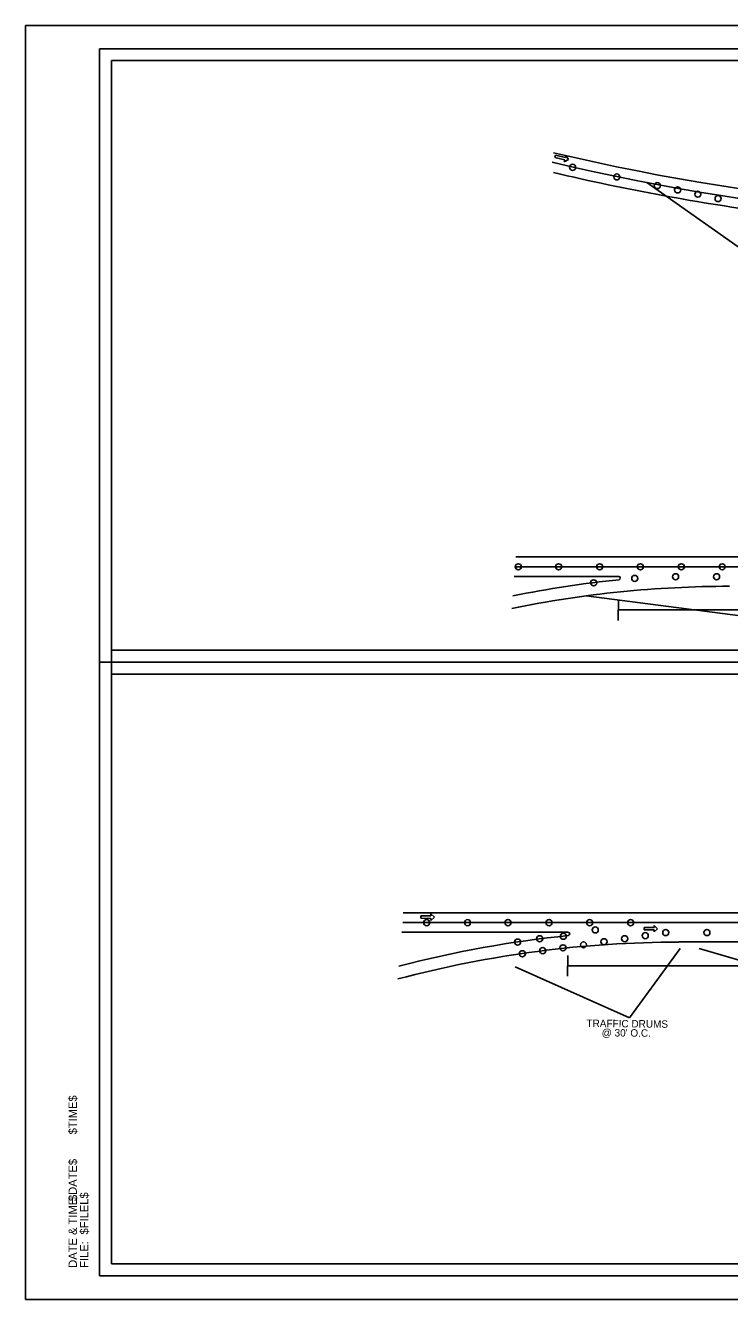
# Model space of a CAD drawing. Extents: x 13528 to 25043, y 7635 to 10612.
# Drawn here: x 17592 to 18181, y 9545 to 10612 of the extents above; entities that cross this region are included whole.
import ezdxf

# ---------------------------------------------------------------- set-up
doc = ezdxf.new("R2010")
doc.units = 0
for name, color, linetype in [('Default', 7, 'Continuous'), ('R_Border', 7, 'Continuous'), ('R_Border Notes', 7, 'Continuous'), ('R_Border Plan-Plan', 7, 'Continuous'), ('R_Draft', 7, 'Continuous'), ('R_Revision Date Text', 7, 'Continuous')]:
    doc.layers.add(name, color=color, linetype=linetype)

# ---------------------------------------------------------------- blocks, each defined once
blk = doc.blocks.new('DOT')
at = {"layer": 'Default'}
blk.add_circle((-0.4, -0.3), 3.75, dxfattribs=at)
blk = doc.blocks.new('SARROW')
at = {"layer": 'Default'}
for p, q in [((15.6, 3.2), (-13.8, 3.2)), ((-13.8, 3.2), (-13.8, -2.8)), ((15.6, 8.2), (15.6, 3.2)), ((15.6, 8.2), (26, 0.2)), ((26, 0.2), (15.6, -7.8)), ((15.6, -2.8), (-13.8, -2.8)), ((15.6, -2.8), (15.6, -7.8))]:
    blk.add_line(p, q, dxfattribs=at)

msp = doc.modelspace()

# ---------------------------------------------------------------- linework, layer by layer
at = {"layer": 'Default'}
for p, q in [((18002.2, 10166.6), (19044, 10166.6)), ((18002, 10158.4), (19043.8, 10158.4)), ((18000.8, 10150.2), (18088.5, 10150.2)), ((18087.7, 10113.5), (18088.1, 10130.9)), ((18087.9, 10122.2), (18737.1, 10122.2)), ((17907.8, 9868.7), (19009.2, 9868.7)), ((17907.6, 9860.5), (19009, 9860.5)), ((17906.5, 9852.3), (17954.2, 9852.3)), ((17954.2, 9852.3), (18046, 9852.3)), ((18138.5, 9844.2), (18695, 9844.2)), ((18045.2, 9815.6), (18045.6, 9833)), ((18045.4, 9824.3), (18694.6, 9824.3))]:
    msp.add_line(p, q, dxfattribs=at)
for centre, major_axis, start_param, end_param in [((18454.4, 13048.2), (0, 2600.9), 2.945637, 3.209664), ((18454.4, 13048.2), (0, 2592.8), 2.945637, 3.209664), ((18454.4, 13048.2), (0, 2609.1), 2.94688, 3.032274), ((18148.8, 8848), (106.5, 1301.2), 0.153253, 0.235336), ((18088.4, 10148.9), (0.11, 1.36), 3.294846, 6.351257), ((18148.8, 8848), (105.6, 1291), 0.068125, 0.237227), ((18106.3, 8550.1), (106.5, 1301.2), 0.153253, 0.284497), ((18046, 9851), (0.11, 1.36), 3.294846, 6.351257), ((18106.3, 8550.1), (105.6, 1291), 0.068125, 0.286803)]:
    msp.add_ellipse(centre, major_axis=major_axis, ratio=0.833333, start_param=start_param, end_param=end_param, dxfattribs=at)
at = {"layer": 'R_Border'}
for p, q in [((18111.7, 10480), (18237.7, 10391.1)), ((18060.9, 10134), (18457.7, 10082.5)), ((18139.6, 9838.7), (18097.1, 9780.6)), ((18155.5, 9838.8), (18383.8, 9771.7)), ((18001.6, 9823.3), (18097.1, 9780.6))]:
    msp.add_line(p, q, dxfattribs=at)
at = {"layer": 'R_Border Plan-Plan'}
msp.add_line((17653.6, 10078.4), (19234.5, 10078.4), dxfattribs=at)
at = {"layer": 'R_Draft'}
for p, q in [((17653.6, 10592.1), (19234.5, 10592.1)), ((17653.6, 9564.8), (17653.6, 10592.1)), ((17653.6, 9564.8), (17653.6, 9564.8)), ((19234.5, 9564.8), (17653.6, 9564.8))]:
    msp.add_line(p, q, dxfattribs=at)
at = {"layer": 'R_Revision Date Text'}
for points in [[(17591.6, 10611.5), (19258.3, 10611.5), (19258.3, 9544.9), (17591.6, 9544.9)], [(19224.5, 10088.4), (17663.6, 10088.4), (17663.6, 10582.1), (18911.3, 10582.1), (18911.3, 10532.7), (18999, 10532.7), (19119.5, 10532.7), (19119.5, 10421), (19224.5, 10421)], [(17663.6, 10582.1), (18911.3, 10582.1), (18911.3, 10532.7), (18999, 10532.7), (19119.5, 10532.7), (19119.5, 10421), (19224.5, 10421), (19224.5, 9574.8), (17663.6, 9574.8)], [(17663.6, 10068.4), (19224.5, 10068.4), (19224.5, 9574.8), (17663.6, 9574.8)]]:
    msp.add_lwpolyline(points, close=True, dxfattribs=at)

# ---------------------------------------------------------------- block references
at = {"layer": 'R_Border'}
for name, p, xscale, yscale, rotation in [('SARROW', (18038.9, 10501), 0.2861447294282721, 0.33757209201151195, -13.600455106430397), ('DOT', (18004.4, 10158.5), 0.6809210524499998, 0.6809210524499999, -4.676990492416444), ('DOT', (18038.1, 10158.5), 0.6809210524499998, 0.6809210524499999, -4.676990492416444), ('DOT', (18072.6, 10158.5), 0.6809210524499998, 0.6809210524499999, -4.676990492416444), ('DOT', (18106.6, 10158.5), 0.6809210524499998, 0.6809210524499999, -4.676990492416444), ('DOT', (18140.9, 10158.5), 0.6809210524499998, 0.6809210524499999, -4.676990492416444), ('DOT', (18175.1, 10158.5), 0.6809210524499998, 0.6809210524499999, -4.676990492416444), ('DOT', (18067.6, 10145.1), 0.6809210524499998, 0.6809210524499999, -4.676990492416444), ('DOT', (18101.9, 10148.8), 0.6809210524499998, 0.6809210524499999, -4.676990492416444), ('DOT', (18136.1, 10150.2), 0.6809210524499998, 0.6809210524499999, -4.676990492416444), ('DOT', (18170.4, 10150.2), 0.6809210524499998, 0.6809210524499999, -4.676990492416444), ('SARROW', (17926.5, 9865), 0.283940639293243, 0.3401924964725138, -0.5613379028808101), ('DOT', (17927.8, 9860.6), 0.6809210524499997, 0.6809210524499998, -4.676990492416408), ('DOT', (17961.9, 9860.6), 0.6809210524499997, 0.6809210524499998, -4.676990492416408), ('DOT', (17995.7, 9860.6), 0.6809210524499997, 0.6809210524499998, -4.676990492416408), ('DOT', (18030.2, 9860.6), 0.6809210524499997, 0.6809210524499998, -4.676990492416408), ('DOT', (18064.1, 9860.6), 0.6809210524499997, 0.6809210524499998, -4.676990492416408), ('DOT', (18068.8, 9854.5), 0.6809210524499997, 0.6809210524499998, -4.676990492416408), ('DOT', (18098.4, 9860.6), 0.6809210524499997, 0.6809210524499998, -4.676990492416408), ('SARROW', (18113.4, 9855.3), 0.28398470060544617, 0.3401397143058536, -0.17370681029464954), ('DOT', (18003.8, 9844.3), 0.6809210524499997, 0.6809210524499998, -4.676990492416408), ('DOT', (18022.3, 9847.1), 0.6809210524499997, 0.6809210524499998, -4.676990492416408), ('DOT', (18042.2, 9849.2), 0.6809210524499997, 0.6809210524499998, -4.676990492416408), ('DOT', (18076.2, 9844.6), 0.6809210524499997, 0.6809210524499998, -4.676990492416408), ('DOT', (18093.5, 9847.1), 0.6809210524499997, 0.6809210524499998, -4.676990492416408), ('DOT', (18110.7, 9849.7), 0.6809210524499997, 0.6809210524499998, -4.676990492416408), ('DOT', (18127.9, 9852.3), 0.6809210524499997, 0.6809210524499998, -4.676990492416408), ('DOT', (18162.3, 9852.3), 0.6809210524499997, 0.6809210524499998, -4.676990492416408), ('DOT', (18007.8, 9834.5), 0.6809210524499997, 0.6809210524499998, -4.676990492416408), ('DOT', (18024.9, 9837.1), 0.6809210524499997, 0.6809210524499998, -4.676990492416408), ('DOT', (18041.8, 9839.5), 0.6809210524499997, 0.6809210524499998, -4.676990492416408), ('DOT', (18059, 9842), 0.6809210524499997, 0.6809210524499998, -4.676990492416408)]:
    msp.add_blockref(name, p, dxfattribs=dict(at, xscale=xscale, yscale=yscale, rotation=rotation))
at = {"layer": 'R_Border', "xscale": 0.6809210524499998, "yscale": 0.6809210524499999}
for p in [(18049.8, 10493), (18086.9, 10485), (18120.8, 10477.7), (18137.8, 10474.1), (18154.7, 10470.5), (18171.7, 10466.8)]:
    msp.add_blockref('DOT', p, dxfattribs=at)

# ---------------------------------------------------------------- texts
at = {"layer": 'R_Border'}
for s, p in [('TRAFFIC DRUMS ', (18061.2, 9773)), ("@ 30' O.C.", (18073.9, 9765.2))]:
    msp.add_text(s, height=6.25, rotation=359.4579, dxfattribs=at).set_placement(p)
at = {"layer": 'R_Border Notes'}
for s, height, p in [('$TIME$', 6.98, (17634.6, 9683.1)), ('$DATE$', 6.98, (17634.6, 9627.3)), ('$FILEL$', 6.98, (17644.2, 9599.3)), ('DATE & TIME:', 6.984, (17634.6, 9571.4)), ('FILE: ', 6.98, (17644.2, 9571.4))]:
    msp.add_text(s, height=height, rotation=90, dxfattribs=at).set_placement(p)

doc.saveas('drawing.dxf')
